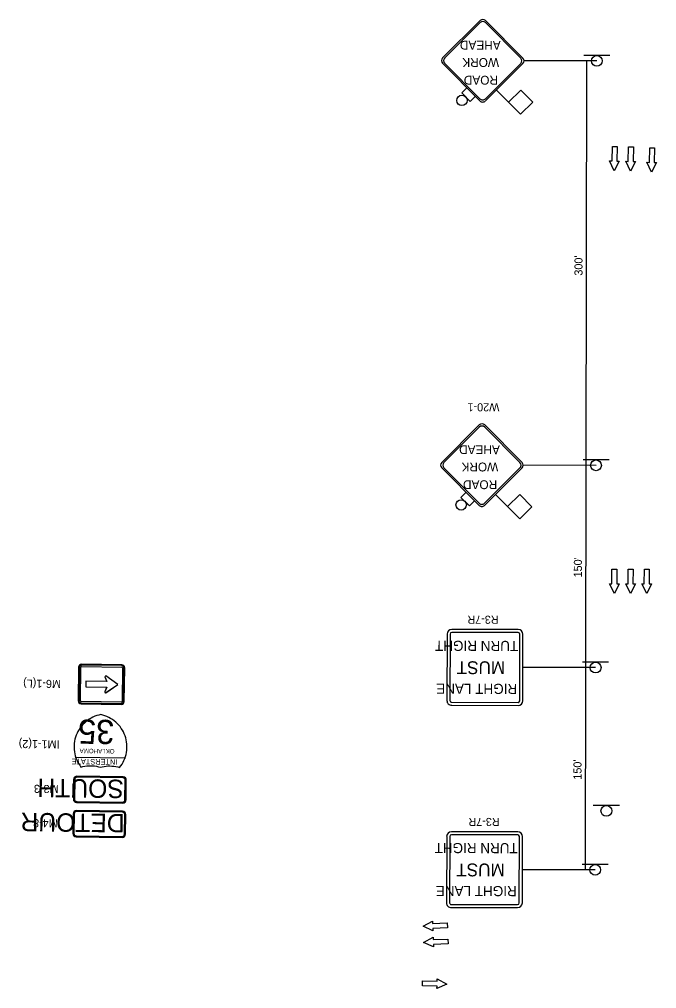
# Model space of a CAD drawing. Extents: x 2135767 to 2151731, y 141839 to 175894.
# Drawn here: x 2150232 to 2150705, y 145619 to 146338 of the extents above; entities that cross this region are included whole.
import ezdxf

# ---------------------------------------------------------------- set-up
doc = ezdxf.new("R2010")
doc.units = 0
for name, color, linetype in [('Default', 7, 'Continuous'), ('PR_Dimensions_Phase1', 7, 'Continuous'), ('PR_Phasing_Detour_1', 7, 'Continuous'), ('PR_Phasing_Traffic_Control_Devices_1', 7, 'Continuous'), ('Pr_Traffic_Arrows_Phase_1', 7, 'Continuous'), ('PR_Traffic_Sign_Temp', 7, 'Continuous'), ('PR_Txt', 7, 'Continuous'), ('PR_Txt_Phase_1', 7, 'Continuous')]:
    doc.layers.add(name, color=color, linetype=linetype)

# ---------------------------------------------------------------- blocks, each defined once
blk = doc.blocks.new('FLSHFLAG')
at = {"layer": 'PR_Txt'}
for p, q in [((-1.2, 14.13), (0.84, 16.15)), ((0.84, 16.15), (4.9, 12.08)), ((0.82, 12.08), (-1.2, 14.13)), ((0.82, 12.08), (2.86, 14.11)), ((9.26, 14), (8.4, 13.15)), ((9.26, 14), (10.68, 12.58)), ((10.68, 12.58), (9.83, 11.72))]:
    blk.add_line(p, q, dxfattribs=at)
blk.add_circle((10.65, 13.84), 0.873, dxfattribs=at)

msp = doc.modelspace()

# ---------------------------------------------------------------- linework, layer by layer
at = {"layer": 'PR_Dimensions_Phase1'}
for p, q in [((2150660.41, 146306.88), (2150606.27, 146306.92)), ((2150659.81, 146006.88), (2150605.81, 146006.93)), ((2150659.51, 145856.88), (2150605.51, 145856.93)), ((2150659.21, 145706.88), (2150605.21, 145706.93))]:
    msp.add_line(p, q, dxfattribs=at)
msp.add_lwpolyline([(2150651.9, 145706.89), (2150653.1, 146306.89)], dxfattribs=at)
at = {"layer": 'PR_Phasing_Detour_1'}
for p, q in [((2150275.94, 145857.16), (2150275.62, 145832.19)), ((2150276.55, 145857.16), (2150276.23, 145832.18)), ((2150276.55, 145857.16), (2150276.23, 145832.18)), ((2150277.24, 145832.17), (2150277.57, 145857.14)), ((2150277.24, 145832.17), (2150277.57, 145857.14)), ((2150278.11, 145857.67), (2150307.97, 145857.29)), ((2150278.11, 145857.67), (2150307.97, 145857.29)), ((2150307.98, 145858.3), (2150278.12, 145858.69)), ((2150307.98, 145858.3), (2150278.12, 145858.69)), ((2150307.99, 145858.91), (2150278.13, 145859.3)), ((2150308.5, 145856.74), (2150308.17, 145831.77)), ((2150308.5, 145856.74), (2150308.17, 145831.77)), ((2150309.19, 145831.76), (2150309.51, 145856.73)), ((2150309.19, 145831.76), (2150309.51, 145856.73)), ((2150309.8, 145831.75), (2150310.12, 145856.72)), ((2150281.33, 145846.69), (2150281.28, 145842.52)), ((2150296.81, 145846.49), (2150281.33, 145846.69)), ((2150295.47, 145849.97), (2150296.81, 145846.49)), ((2150305.11, 145844.3), (2150296.17, 145850.66)), ((2150281.28, 145842.52), (2150296.76, 145842.32)), ((2150296.76, 145842.32), (2150295.33, 145838.87)), ((2150296.01, 145838.17), (2150305.11, 145844.3)), ((2150277.75, 145830), (2150307.61, 145829.61)), ((2150277.76, 145830.61), (2150307.62, 145830.22)), ((2150277.76, 145830.61), (2150307.62, 145830.22)), ((2150307.63, 145831.24), (2150277.77, 145831.63)), ((2150307.63, 145831.24), (2150277.77, 145831.63)), ((2150310.67, 145789.77), (2150273.49, 145790.25)), ((2150308.92, 145775.06), (2150274.74, 145775.5)), ((2150308.93, 145775.87), (2150274.75, 145776.31)), ((2150272.27, 145773.9), (2150272.08, 145759.25)), ((2150273.09, 145773.89), (2150272.9, 145759.24)), ((2150310.34, 145758.76), (2150310.53, 145773.41)), ((2150311.15, 145758.75), (2150311.34, 145773.4)), ((2150274.49, 145756.78), (2150308.68, 145756.34)), ((2150274.5, 145757.59), (2150308.69, 145757.15)), ((2150667.45, 145754.59), (2150657.8, 145754.49)), ((2150677.1, 145754.7), (2150667.45, 145754.59)), ((2150271.87, 145748.45), (2150271.68, 145733.8)), ((2150272.68, 145748.44), (2150272.49, 145733.79)), ((2150308.52, 145749.6), (2150274.33, 145750.05)), ((2150308.53, 145750.42), (2150274.34, 145750.86)), ((2150309.94, 145733.3), (2150310.12, 145747.96)), ((2150310.75, 145733.29), (2150310.94, 145747.95)), ((2150274.09, 145731.33), (2150308.28, 145730.88)), ((2150274.1, 145732.14), (2150308.29, 145731.7))]:
    msp.add_line(p, q, dxfattribs=at)
for points in [[(2150295.52, 145849.97), (2150296.87, 145846.49), (2150281.38, 145846.69), (2150281.33, 145842.52), (2150296.81, 145842.32), (2150295.38, 145838.87)], [(2150305.16, 145844.3), (2150296.23, 145850.66)], [(2150296.07, 145838.17), (2150305.16, 145844.3)], [(2150306.35, 145782.76), (2150307.3, 145784), (2150308.16, 145785.3), (2150308.93, 145786.65), (2150309.62, 145788.05), (2150310.22, 145789.48), (2150310.72, 145790.96), (2150311.13, 145792.46), (2150311.45, 145793.98), (2150311.66, 145795.52), (2150311.78, 145797.08), (2150311.8, 145798.63), (2150311.72, 145800.19), (2150311.54, 145801.74), (2150311.26, 145803.27), (2150310.88, 145804.78), (2150310.41, 145806.26), (2150309.85, 145807.71), (2150309.19, 145809.13), (2150308.45, 145810.49), (2150307.62, 145811.81), (2150306.71, 145813.07), (2150305.71, 145814.27), (2150304.65, 145815.41), (2150303.51, 145816.47), (2150302.31, 145817.46), (2150301.05, 145818.38), (2150299.73, 145819.21), (2150298.37, 145819.95), (2150296.95, 145820.61), (2150295.5, 145821.17), (2150294.02, 145821.64), (2150292.51, 145822.02), (2150290.99, 145821.68), (2150289.49, 145821.25), (2150288.02, 145820.72), (2150286.6, 145820.1), (2150285.21, 145819.39), (2150283.87, 145818.6), (2150282.59, 145817.72), (2150281.36, 145816.76), (2150280.2, 145815.72), (2150279.1, 145814.62), (2150278.08, 145813.44), (2150277.14, 145812.2), (2150276.27, 145810.91), (2150275.49, 145809.56), (2150274.8, 145808.17), (2150274.2, 145806.73), (2150273.69, 145805.26), (2150273.27, 145803.76), (2150272.96, 145802.23), (2150272.74, 145800.69), (2150272.62, 145799.14), (2150272.59, 145797.58), (2150272.67, 145796.03), (2150272.85, 145794.48), (2150273.12, 145792.95), (2150273.49, 145791.44), (2150273.96, 145789.95), (2150274.52, 145788.5), (2150275.17, 145787.09), (2150275.91, 145785.72), (2150276.74, 145784.4), (2150277.65, 145783.13), (2150279.06, 145783.5), (2150280.49, 145783.78), (2150281.93, 145783.98), (2150283.38, 145784.09), (2150284.84, 145784.12), (2150286.29, 145784.06), (2150287.74, 145783.91), (2150289.18, 145783.67), (2150290.6, 145783.35), (2150292, 145782.95), (2150293.41, 145783.31), (2150294.84, 145783.6), (2150296.28, 145783.8), (2150297.73, 145783.91), (2150299.19, 145783.93), (2150300.65, 145783.87), (2150302.1, 145783.72), (2150303.53, 145783.49), (2150304.95, 145783.17), (2150306.35, 145782.76)]]:
    msp.add_lwpolyline(points, dxfattribs=at)
msp.add_circle((2150667.49, 145750.6), 4, dxfattribs=at)
for centre, radius, start, end in [((2150278.1, 145857.14), 2.16, 89.25897, 179.25897), ((2150278.1, 145857.14), 1.55, 89.25897, 179.25897), ((2150278.1, 145857.14), 1.55, 89.25897, 179.25897), ((2150278.1, 145857.14), 0.537, 89.25897, 179.25897), ((2150278.1, 145857.14), 0.537, 89.25897, 179.25897), ((2150307.96, 145856.75), 0.537, 359.25897, 89.25897), ((2150307.96, 145856.75), 0.537, 359.25897, 89.25897), ((2150307.96, 145856.75), 1.55, 359.25897, 89.25897), ((2150307.96, 145856.75), 1.55, 359.25897, 89.25897), ((2150307.96, 145856.75), 2.16, 359.25897, 89.25897), ((2150296.17, 145849.96), 0.694, 89.25897, 179.25897), ((2150296.22, 145849.96), 0.694, 89.25897, 179.25897), ((2150277.78, 145832.16), 2.16, 179.25897, 269.25897), ((2150277.78, 145832.16), 1.55, 179.25897, 269.25897), ((2150277.78, 145832.16), 1.55, 179.25897, 269.25897), ((2150277.78, 145832.16), 0.537, 179.25897, 269.25897), ((2150277.78, 145832.16), 0.537, 179.25897, 269.25897), ((2150296.02, 145838.86), 0.694, 179.25897, 269.25897), ((2150296.07, 145838.86), 0.694, 179.25897, 269.25897), ((2150307.64, 145831.78), 2.16, 269.25897, 359.25897), ((2150307.64, 145831.78), 1.55, 269.25897, 359.25897), ((2150307.64, 145831.78), 1.55, 269.25897, 359.25897), ((2150307.64, 145831.78), 0.537, 269.25897, 359.25897), ((2150307.64, 145831.78), 0.537, 269.25897, 359.25897), ((2150274.71, 145773.87), 2.44, 89.25897, 179.25897), ((2150274.71, 145773.87), 1.63, 89.25897, 179.25897), ((2150308.9, 145773.43), 1.63, 359.25897, 89.25897), ((2150308.9, 145773.43), 2.44, 359.25897, 89.25897), ((2150274.53, 145759.22), 2.44, 179.25897, 269.25897), ((2150274.53, 145759.22), 1.63, 179.25897, 269.25897), ((2150308.71, 145758.78), 2.44, 269.25897, 359.25897), ((2150308.71, 145758.78), 1.63, 269.25897, 359.25897), ((2150274.31, 145748.42), 2.44, 89.25897, 179.25897), ((2150274.31, 145748.42), 1.63, 89.25897, 179.25897), ((2150308.5, 145747.98), 1.63, 359.25897, 89.25897), ((2150308.5, 145747.98), 2.44, 359.25897, 89.25897), ((2150274.12, 145733.77), 2.44, 179.25897, 269.25897), ((2150274.12, 145733.77), 1.63, 179.25897, 269.25897), ((2150308.31, 145733.33), 2.44, 269.25897, 359.25897), ((2150308.31, 145733.33), 1.63, 269.25897, 359.25897)]:
    msp.add_arc(centre, radius, start, end, dxfattribs=at)
at = {"layer": 'PR_Phasing_Traffic_Control_Devices_1'}
for p, q in [((2150573.83, 146336.83), (2150545.93, 146309.04)), ((2150573.83, 146335.24), (2150547.52, 146309.04)), ((2150604, 146308.92), (2150577.8, 146335.23)), ((2150605.59, 146308.92), (2150577.81, 146336.82)), ((2150545.92, 146305.06), (2150573.71, 146277.17)), ((2150547.51, 146305.06), (2150573.71, 146278.76)), ((2150577.69, 146278.75), (2150603.99, 146304.95)), ((2150577.69, 146277.16), (2150605.58, 146304.94)), ((2150573.23, 146036.83), (2150545.33, 146009.04)), ((2150573.22, 146035.24), (2150546.92, 146009.04)), ((2150604.99, 146008.92), (2150577.2, 146036.82)), ((2150603.4, 146008.92), (2150577.2, 146035.23)), ((2150545.32, 146005.06), (2150573.11, 145977.17)), ((2150546.91, 146005.06), (2150573.11, 145978.76)), ((2150577.08, 145977.16), (2150604.98, 146004.94)), ((2150577.09, 145978.75), (2150603.39, 146004.95)), ((2150659.81, 146010.88), (2150650.16, 146010.89)), ((2150669.46, 146010.88), (2150659.81, 146010.88)), ((2150602.05, 145885.06), (2150552.83, 145885.16)), ((2150602.04, 145882.81), (2150552.83, 145882.91)), ((2150549.31, 145881.65), (2150549.21, 145832.44)), ((2150551.56, 145881.65), (2150551.46, 145832.43)), ((2150603.21, 145832.33), (2150603.31, 145881.55)), ((2150605.46, 145832.32), (2150605.56, 145881.54)), ((2150659.51, 145860.88), (2150649.86, 145860.89)), ((2150669.16, 145860.88), (2150659.51, 145860.88)), ((2150552.72, 145831.16), (2150601.94, 145831.06)), ((2150552.72, 145828.91), (2150601.94, 145828.81)), ((2150549.01, 145731.65), (2150548.91, 145682.44)), ((2150551.26, 145731.65), (2150551.16, 145682.43)), ((2150601.74, 145732.81), (2150552.52, 145732.91)), ((2150601.75, 145735.06), (2150552.53, 145735.16)), ((2150602.91, 145682.33), (2150603.01, 145731.55)), ((2150605.16, 145682.32), (2150605.26, 145731.54)), ((2150659.21, 145710.88), (2150649.56, 145710.89)), ((2150668.86, 145710.88), (2150659.21, 145710.88)), ((2150552.42, 145681.16), (2150601.64, 145681.06)), ((2150552.42, 145678.91), (2150601.63, 145678.81))]:
    msp.add_line(p, q, dxfattribs=at)
for centre in [(2150659.81, 146006.88), (2150659.51, 145856.88), (2150659.21, 145706.88)]:
    msp.add_circle(centre, 4, dxfattribs=at)
for centre, radius, start, end in [((2150575.81, 146334.83), 2.81, 44.88481, 134.88481), ((2150575.81, 146333.24), 2.81, 44.88481, 134.88481), ((2150547.92, 146307.05), 2.81, 134.88481, 224.88481), ((2150549.51, 146307.04), 2.81, 134.88481, 224.88481), ((2150602.01, 146306.94), 2.81, 314.88481, 44.88481), ((2150603.6, 146306.94), 2.81, 314.88481, 44.88481), ((2150575.71, 146280.74), 2.81, 224.88481, 314.88481), ((2150575.7, 146279.15), 2.81, 224.88481, 314.88481), ((2150575.21, 146033.24), 2.81, 44.88481, 134.88481), ((2150575.21, 146034.83), 2.81, 44.88481, 134.88481), ((2150547.31, 146007.05), 2.81, 134.88481, 224.88481), ((2150548.9, 146007.05), 2.81, 134.88481, 224.88481), ((2150601.41, 146006.94), 2.81, 314.88481, 44.88481), ((2150603, 146006.94), 2.81, 314.88481, 44.88481), ((2150575.1, 145980.74), 2.81, 224.88481, 314.88481), ((2150575.1, 145979.15), 2.81, 224.88481, 314.88481), ((2150552.82, 145881.65), 3.52, 89.88481, 179.88481), ((2150552.82, 145881.65), 1.27, 89.88481, 179.88481), ((2150602.04, 145881.55), 1.27, 359.88481, 89.88481), ((2150602.04, 145881.55), 3.52, 359.88481, 89.88481), ((2150552.72, 145832.43), 3.52, 179.88481, 269.88481), ((2150552.72, 145832.43), 1.27, 179.88481, 269.88481), ((2150601.94, 145832.33), 1.27, 269.88481, 359.88481), ((2150601.94, 145832.33), 3.52, 269.88481, 359.88481), ((2150552.52, 145731.65), 3.52, 89.88481, 179.88481), ((2150552.52, 145731.65), 1.27, 89.88481, 179.88481), ((2150601.74, 145731.55), 1.27, 359.88481, 89.88481), ((2150601.74, 145731.55), 3.52, 359.88481, 89.88481), ((2150552.42, 145682.43), 3.52, 179.88481, 269.88481), ((2150552.42, 145682.43), 1.27, 179.88481, 269.88481), ((2150601.64, 145682.33), 3.52, 269.88481, 359.88481), ((2150601.64, 145682.33), 1.27, 269.88481, 359.88481)]:
    msp.add_arc(centre, radius, start, end, dxfattribs=at)
at = {"layer": 'Pr_Traffic_Arrows_Phase_1'}
for p, q in [((2150671.66, 146232.64), (2150671.91, 146243.44)), ((2150671.91, 146243.44), (2150675.51, 146243.36)), ((2150675.51, 146243.36), (2150675.26, 146232.56)), ((2150683.66, 146232.36), (2150683.91, 146243.16)), ((2150683.91, 146243.16), (2150687.51, 146243.08)), ((2150687.51, 146243.08), (2150687.26, 146232.28)), ((2150699.36, 146231.57), (2150699.68, 146242.37)), ((2150699.68, 146242.37), (2150703.28, 146242.26)), ((2150703.28, 146242.26), (2150702.96, 146231.46)), ((2150673.29, 146225.4), (2150669.86, 146232.68)), ((2150669.86, 146232.68), (2150671.66, 146232.64)), ((2150677.06, 146232.52), (2150673.29, 146225.4)), ((2150675.26, 146232.56), (2150677.06, 146232.52)), ((2150685.29, 146225.12), (2150681.86, 146232.41)), ((2150681.86, 146232.41), (2150683.66, 146232.36)), ((2150689.06, 146232.24), (2150685.29, 146225.12)), ((2150687.26, 146232.28), (2150689.06, 146232.24)), ((2150700.95, 146224.32), (2150697.56, 146231.63)), ((2150697.56, 146231.63), (2150699.36, 146231.57)), ((2150704.76, 146231.41), (2150700.95, 146224.32)), ((2150702.96, 146231.46), (2150704.76, 146231.41)), ((2150671.63, 145919.02), (2150671.65, 145929.82)), ((2150671.65, 145929.82), (2150675.25, 145929.81)), ((2150675.25, 145929.81), (2150675.23, 145919.01)), ((2150683.63, 145919), (2150683.65, 145929.8)), ((2150683.65, 145929.8), (2150687.25, 145929.79)), ((2150687.25, 145929.79), (2150687.23, 145918.99)), ((2150695.63, 145918.97), (2150695.65, 145929.77)), ((2150695.65, 145929.77), (2150699.25, 145929.77)), ((2150699.25, 145929.77), (2150699.23, 145918.97)), ((2150673.41, 145911.82), (2150669.83, 145919.02)), ((2150669.83, 145919.02), (2150671.63, 145919.02)), ((2150677.03, 145919.01), (2150673.41, 145911.82)), ((2150675.23, 145919.01), (2150677.03, 145919.01)), ((2150685.41, 145911.79), (2150681.83, 145919)), ((2150681.83, 145919), (2150683.63, 145919)), ((2150689.03, 145918.99), (2150685.41, 145911.79)), ((2150687.23, 145918.99), (2150689.03, 145918.99)), ((2150697.41, 145911.77), (2150693.83, 145918.98)), ((2150693.83, 145918.98), (2150695.63, 145918.97)), ((2150701.03, 145918.96), (2150697.41, 145911.77)), ((2150699.23, 145918.97), (2150701.03, 145918.96)), ((2150531.46, 145664.99), (2150538.52, 145668.87)), ((2150538.52, 145668.87), (2150538.59, 145667.07)), ((2150538.59, 145667.07), (2150549.38, 145667.49)), ((2150549.38, 145667.49), (2150549.52, 145663.9)), ((2150538.8, 145661.68), (2150531.46, 145664.99)), ((2150549.52, 145663.9), (2150538.73, 145663.47)), ((2150538.73, 145663.47), (2150538.8, 145661.68)), ((2150531.93, 145653), (2150538.98, 145656.88)), ((2150539.27, 145649.68), (2150531.93, 145653)), ((2150538.98, 145656.88), (2150539.05, 145655.08)), ((2150539.05, 145655.08), (2150549.85, 145655.5)), ((2150549.85, 145655.5), (2150549.99, 145651.9)), ((2150549.99, 145651.9), (2150539.19, 145651.48)), ((2150539.19, 145651.48), (2150539.27, 145649.68)), ((2150531.04, 145620.87), (2150531.14, 145624.47)), ((2150531.14, 145624.47), (2150541.94, 145624.17)), ((2150541.94, 145624.17), (2150541.99, 145625.97)), ((2150541.99, 145625.97), (2150549.09, 145622.17)), ((2150541.84, 145620.57), (2150531.04, 145620.87)), ((2150549.09, 145622.17), (2150541.79, 145618.77)), ((2150541.79, 145618.77), (2150541.84, 145620.57))]:
    msp.add_line(p, q, dxfattribs=at)
at = {"layer": 'PR_Traffic_Sign_Temp'}
for p, q in [((2150660.42, 146310.88), (2150650.77, 146310.89)), ((2150670.07, 146310.87), (2150660.42, 146310.88))]:
    msp.add_line(p, q, dxfattribs=at)
msp.add_circle((2150660.41, 146306.88), 4, dxfattribs=at)

# ---------------------------------------------------------------- block references
at = {"layer": 'PR_Phasing_Traffic_Control_Devices_1', "xscale": 4.429125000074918, "yscale": 4.429125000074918, "rotation": 179.88480796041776}
for p in [(2150607.64, 146338.75), (2150607.04, 146038.75)]:
    msp.add_blockref('FLSHFLAG', p, dxfattribs=at)

# ---------------------------------------------------------------- texts
at = {"layer": 'Default'}
msp.add_text("300'", height=6, rotation=89.88481, dxfattribs=at).set_placement((2150649.78, 146147.58))
at = {"layer": 'PR_Phasing_Detour_1'}
for s, height, p in [('M6-1(L)', 6, (2150262.91, 145847.66)), ('35', 17.974, (2150302.5, 145818.05)), ('IM1-1(2)', 6, (2150261.87, 145802.84)), ('OKLAHOMA', 3.31, (2150302.63, 145796.41)), ('INTERSTATE', 4.084, (2150304.71, 145788.86)), ('SOUTH', 13.675, (2150309.54, 145773.69)), ('M3-3', 6, (2150261.13, 145769.72)), ('DETOUR', 13.675, (2150310.18, 145748.23)), ('M4-8', 6, (2150260.48, 145744.27))]:
    msp.add_text(s, height=height, rotation=179.25897, dxfattribs=at).set_placement(p)
at = {"layer": 'PR_Phasing_Traffic_Control_Devices_1'}
for s, height, p in [('AHEAD', 6.562, (2150589.07, 146321.72)), ('WORK', 6.562, (2150587.88, 146308.92)), ('ROAD', 6.562, (2150587.07, 146295.8)), ('AHEAD', 6.562, (2150588.47, 146021.72)), ('WORK', 6.562, (2150587.28, 146008.92)), ('ROAD', 6.562, (2150586.47, 145995.8)), ('TURN RIGHT', 7.485, (2150602.07, 145876.66)), ('MUST', 9.503, (2150592.44, 145861.5)), ('RIGHT LANE', 7.485, (2150601.33, 145844.81)), ('TURN RIGHT', 7.485, (2150601.76, 145726.66)), ('MUST', 9.503, (2150592.14, 145711.5)), ('RIGHT LANE', 7.485, (2150601.03, 145694.81))]:
    msp.add_text(s, height=height, rotation=179.88481, dxfattribs=at).set_placement(p)
at = {"layer": 'PR_Txt_Phase_1'}
for s, rotation, p in [('W20-1', 179.94956, (2150588.11, 146052.92)), ("150'", 89.88481, (2150649.33, 145923.74)), ('R3-7R', 179.94956, (2150587.56, 145895.36)), ("150'", 89.88481, (2150649.03, 145773.74)), ('R3-7R', 179.94956, (2150588.35, 145745.36))]:
    msp.add_text(s, height=6, rotation=rotation, dxfattribs=at).set_placement(p)

doc.saveas('drawing.dxf')
